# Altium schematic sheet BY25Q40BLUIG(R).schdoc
size 127 x 101 mm
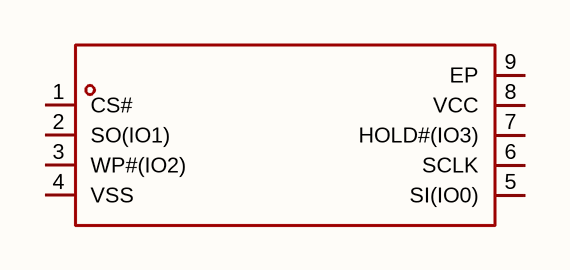
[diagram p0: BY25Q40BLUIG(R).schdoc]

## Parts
U?  by25q40bluig(r)  [USON-8_L3.0-W2.0-P0.50-BL-EP_P25XX]  (value not drawn)

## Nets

Not connected (* = marked no-connect by the designer): U? 1(CS#) 2(SO(IO1)) 3(WP#(IO2)) 4(VSS) 5(SI(IO0)) 6(SCLK) 7(HOLD#(IO3)) 8(VCC) 9(EP)

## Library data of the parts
U? = by25q40bluig(r): 接口类型:SPI;存储容量:4Mbit;时钟频率(fc):85MHz;; Manufacturer: BOYAMICRO(博雅); AddInBom: yes; ModelId: 12a239e5c7384371915ecb51201bf581; ModelName: USON-8_L3.0-W2.0-H0.6-P0.50; ModelTransform: 118.8974,78.74,0,90,0,0,0,0,0; Interface: SPI; Memory Size: 4Mbit; Clock Frequency: 85MHz; Voltage - Supply: 1.65V~2V; Standby Supply Current: 0.6uA; Program / Erase Cycles: 100000次; Page Programming Time (Tpp): 2ms; Block Erase Time(tBE): 8ms; Data Retention - TDR (Year): 20年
